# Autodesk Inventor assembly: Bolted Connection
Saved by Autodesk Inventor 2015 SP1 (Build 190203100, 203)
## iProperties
Created: 2011-06
Part Number: Bolted Connection
Document SubType Name: Assembly
Designer: Guilherme Augusto Franco de Souza
ClientObjectVersion: 1
Author: Guilherme Augusto Franco de Souza
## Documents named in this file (1)
- E:\Visitor Experience Project\WSI2015 - Visitor Experience Project\#46- Sheet Metal Technology\01- 3D Models\Outodoor Heater\2- Assemblies\Outdoor Burner\Design Accelerator\Bolted Connection2.iam
